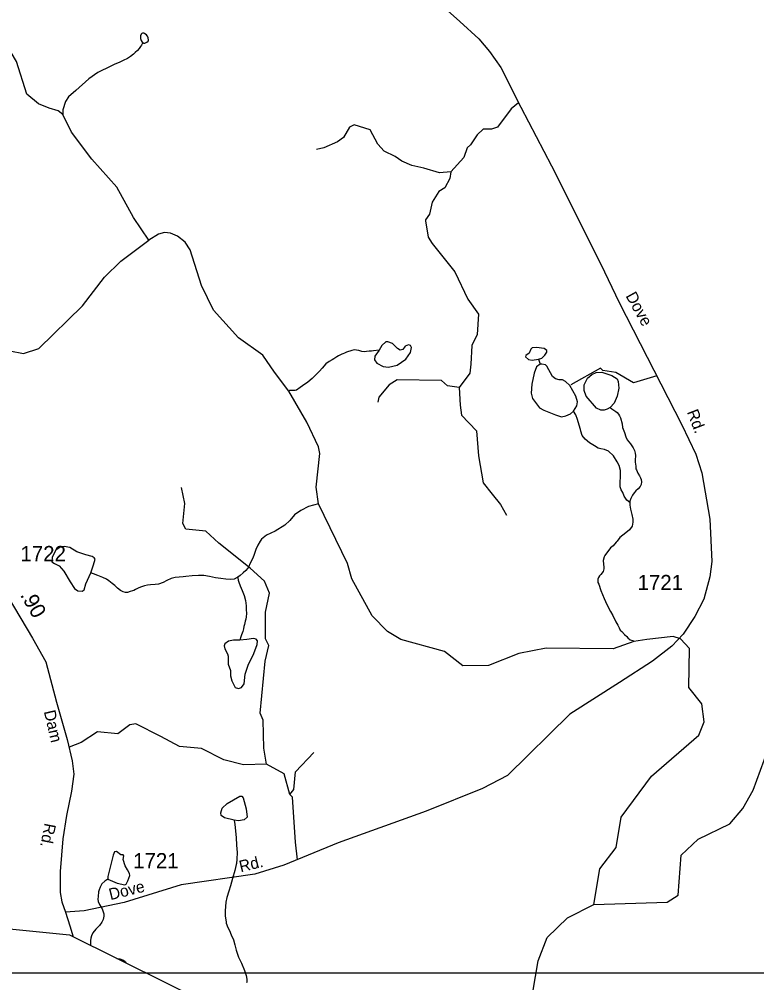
# Model space of a CAD drawing. Extents: x 2056842 to 2160602, y 826753 to 1016856.
# Drawn here: x 2093202 to 2099244, y 845771 to 853660 of the extents above; entities that cross this region are included whole.
import ezdxf

# ---------------------------------------------------------------- set-up
doc = ezdxf.new("R2010")
doc.units = 0
for name, color, linetype in [('Exist Boundary Political CountyLine', 7, 'Continuous'), ('Exist Hydrographic Creek Single Shore', 7, 'Continuous'), ('Exist Hydrographic Misc Water Feature', 7, 'Continuous'), ('Exist Road Non-System Type 51', 7, 'Continuous'), ('Exist Road Secondary Mileage Hundredths English Label', 7, 'Continuous'), ('Exist Road Secondary Type 51 Attributed', 7, 'Continuous'), ('Exist Road Secondary Type 51 Label', 7, 'Continuous'), ('Exist Road Secondary Type 51 Number Label', 7, 'Continuous'), ('Map Preparation Inset Cut Line', 7, 'Continuous')]:
    doc.layers.add(name, color=color, linetype=linetype)

msp = doc.modelspace()

# ---------------------------------------------------------------- linework, layer by layer
at = {"layer": 'Exist Boundary Political CountyLine'}
msp.add_lwpolyline([(2087202.4, 846841.6), (2088278.5, 846703.3), (2089060.9, 846620.9), (2089592.9, 846564), (2090401.1, 846475.5), (2091507.2, 846371.9), (2092417.4, 846283.6), (2093037.6, 846221), (2093614.4, 846162.7), (2094823.1, 845562.6), (2096040.2, 844956.3), (2096290.8, 844827.9), (2097736.3, 844110.3), (2098905.5, 843530.6), (2099954.7, 843014.5), (2100389.5, 842806.4), (2101933, 842032.5), (2102162, 841868.8), (2110170.3, 837920.8)], dxfattribs=at)
at = {"layer": 'Exist Hydrographic Creek Single Shore'}
for points in [[(2094262.8, 851850.9), (2094137.2, 852037.8), (2094000.5, 852284.8), (2093797.5, 852514.6), (2093629.1, 852735.1), (2093557.8, 852881.1), (2093520.2, 852910.4), (2093445.5, 852933.2), (2093359.2, 852968.7), (2093264.2, 853045.4), (2093180.1, 853313), (2093099.6, 853448.9), (2092973, 853489.4), (2092829.3, 853562.9), (2092762.2, 853679.2), (2092728.2, 853870.2), (2092751.4, 854356.6), (2092797, 854536.5)], [(2095654.2, 849692.2), (2095635.2, 849828.1), (2095664.1, 850105.4), (2095654.2, 850159.4), (2095558, 850360.9), (2095409.7, 850615.9), (2095292, 850771.6), (2095198.3, 850908.4), (2094999.1, 851052.4), (2094792.7, 851277.9), (2094695.2, 851479.3), (2094600.9, 851772.4), (2094560.4, 851834.4), (2094499.6, 851883.8), (2094441.4, 851907.9), (2094392, 851913), (2094341.3, 851900.3), (2094262.8, 851850.9)], [(2092899.2, 850987.5), (2093237.1, 850923.1), (2093362.2, 850963.2), (2093719.2, 851313.5), (2093899.2, 851549.4), (2094034.7, 851679.9), (2094262.8, 851850.9)], [(2097909.2, 846410.6), (2097958.2, 846704.9), (2098091.1, 846879.4), (2098132.1, 847127.8), (2098381, 847463.9), (2098771, 847797.1), (2098813, 847907.8), (2098795, 848055.8), (2098687.1, 848189.4), (2098694.1, 848507.4), (2098619.1, 848587.7), (2098560, 848605.4), (2098344.1, 848580.3), (2098236.5, 848566.1), (2098069.1, 848503.9), (2097519.2, 848511.9), (2097294, 848467.3), (2097045.1, 848367.5), (2096836.2, 848365.2), (2096686.1, 848483.1), (2096327, 848582.4), (2096219.2, 848647), (2096094.1, 848774.2), (2095926.1, 849079.5), (2095892.1, 849204.9), (2095654.2, 849692.2)], [(2098205.1, 849702.1), (2098203, 849680.1), (2098209.2, 849650), (2098221.5, 849604.3), (2098229.7, 849566.1), (2098229.5, 849542.2), (2098223.3, 849508.2), (2098201.6, 849479.9), (2098171.9, 849454), (2098123.7, 849417.8), (2098100.1, 849387.8), (2098091.9, 849377.6), (2098068.1, 849349.6), (2098046.2, 849331.8), (2098024, 849301.5), (2098012.3, 849289.5), (2097998.4, 849269.6), (2097994.1, 849259.3), (2097986.1, 849229.3), (2097988.3, 849197.3), (2097992.6, 849173.6), (2097992.6, 849159.3), (2097984.9, 849137.4), (2097966.8, 849113.3), (2097954.9, 849103.4), (2097947.1, 849089.2), (2097941, 849075.5), (2097943, 849047.2), (2097949.2, 849033.3), (2097967.2, 848983.4), (2097995.3, 848917.5), (2098015.6, 848867.4), (2098046.2, 848811.7), (2098063.8, 848777.7), (2098090, 848725.8), (2098105.8, 848697.9), (2098116.1, 848678.1), (2098125.9, 848657.9), (2098138.4, 848645.9), (2098160.4, 848621.9), (2098180.7, 848606.3), (2098188.3, 848596.2), (2098208.2, 848580.2), (2098228.5, 848572.2), (2098236.5, 848566.1)], [(2097909.2, 846410.6), (2098509.2, 846431), (2098600, 846488.2), (2098624, 846815.8), (2098765.1, 846947.4), (2099023, 847073.4), (2099131.1, 847199.2), (2099214.1, 847348.3), (2099396, 847840.1)], [(2097373.2, 844551.5), (2097346.1, 845326.3), (2097452.1, 845950.8), (2097526.1, 846142.8), (2097693.1, 846303.5), (2097909.2, 846410.6)]]:
    msp.add_lwpolyline(points, dxfattribs=at)
at = {"layer": 'Exist Hydrographic Misc Water Feature'}
msp.add_line((2097455.1, 850876.2), (2097470.9, 850836.1), dxfattribs=at)
for points in [[(2094214.2, 853469), (2094220.3, 853465.2), (2094231.8, 853463), (2094248, 853471.1), (2094257.8, 853481.4), (2094260.1, 853489.2), (2094257.8, 853507.4), (2094251.7, 853521.2), (2094249.8, 853525.2), (2094243.9, 853533), (2094231.6, 853540.9), (2094223.8, 853545), (2094217.8, 853547.1), (2094211.9, 853547.2), (2094205.5, 853542.8), (2094201.6, 853537), (2094195.5, 853522.9), (2094193.9, 853513), (2094195.9, 853502.9), (2094201.8, 853487), (2094209.6, 853472.9), (2094214.2, 853469)], [(2094214.2, 853469), (2094212.3, 853463.1), (2094203.9, 853449), (2094196.1, 853437.2), (2094184, 853421.1), (2094169.9, 853405), (2094152.4, 853387), (2094138.1, 853374.9), (2094112.2, 853355), (2094088.2, 853338.7), (2094052.6, 853322.6), (2094026.3, 853308.7), (2093980.4, 853290.5), (2093952.7, 853274.4), (2093846.7, 853223.3), (2093770.7, 853171.4), (2093664.3, 853077.7), (2093606.1, 853025.7), (2093579.5, 852987.7), (2093560, 852919.3), (2093559.6, 852915.3), (2093557.6, 852905), (2093558, 852897.3), (2093558, 852889.2), (2093557.8, 852881.1)], [(2096151.2, 850950.3), (2096115.7, 850900.8), (2096111.9, 850870.4), (2096132.2, 850845.1), (2096182.8, 850817.2), (2096225.9, 850812.2), (2096299.3, 850828.6), (2096370.2, 850876.8), (2096408.2, 850932.5), (2096415.8, 850973.1), (2096408.2, 850989.5), (2096391.8, 850993.3), (2096363.9, 850983.2), (2096343.7, 850955.3), (2096323.4, 850950.3), (2096301.9, 850962.9), (2096260.1, 851006), (2096220.8, 851018.7), (2096204.4, 851017.4), (2096172.7, 850988.3), (2096151.2, 850950.3)], [(2096151.2, 850950.3), (2096103.5, 850945.3), (2096087.3, 850943.3), (2096067.4, 850941), (2096047.5, 850939.2), (2096027.2, 850937), (2096009.6, 850938.8), (2095983.3, 850946.9), (2095965.3, 850950.8), (2095947.5, 850952.7), (2095925.5, 850948.7), (2095883.7, 850934.8), (2095867.5, 850924.7), (2095853.7, 850920.7), (2095843.7, 850916.5), (2095817.9, 850904.2), (2095803.7, 850896.2), (2095779.7, 850880.3), (2095765.8, 850872.3), (2095739.7, 850856.4), (2095713.7, 850838), (2095684, 850802), (2095662, 850778.1), (2095628.2, 850745.9), (2095602.1, 850719.8), (2095586.2, 850705.6), (2095562.6, 850685.6), (2095540.2, 850671.5), (2095522.6, 850657.6), (2095502.3, 850645.6), (2095472.8, 850623.4), (2095462.7, 850619.2), (2095452.5, 850619.1), (2095436.7, 850621.1), (2095422.5, 850621.2), (2095414.7, 850619.2), (2095409.7, 850615.9)], [(2097455.1, 850876.2), (2097482.6, 850886.1), (2097507.9, 850910.2), (2097525.6, 850934.3), (2097524.3, 850948.2), (2097502.8, 850963.4), (2097439.5, 850972.3), (2097404.1, 850968.5), (2097392.7, 850959.6), (2097380, 850925.4), (2097350.9, 850907.7), (2097348.3, 850896.3), (2097373.7, 850873.5), (2097404.1, 850868.4), (2097455.1, 850876.2)], [(2097744.1, 850452.2), (2097770, 850494.7), (2097775, 850527.6), (2097761.1, 850573.2), (2097711.7, 850660.6), (2097677.5, 850693.6), (2097653.5, 850708.8), (2097624.4, 850708.8), (2097594, 850715.1), (2097569.9, 850735.4), (2097524.3, 850820.3), (2097512.9, 850830.4), (2097483.8, 850836.7), (2097470.9, 850836.1)], [(2097470.9, 850836.1), (2097439.5, 850812.7), (2097419.3, 850763.2), (2097400.3, 850673.3), (2097395.2, 850599.8), (2097407.9, 850554.2), (2097464.8, 850479.5), (2097500.3, 850457.9), (2097595.2, 850421.2), (2097643.4, 850404.7), (2097681.3, 850412.3), (2097718.1, 850430.1), (2097744.1, 850452.2)], [(2098043.8, 850480.7), (2098018.1, 850466.8), (2097994.1, 850457.9), (2097967.5, 850457.9), (2097930.8, 850475.7), (2097847.2, 850573.2), (2097830.8, 850621.4), (2097830.8, 850667), (2097857.3, 850720.2), (2097892.8, 850750.6), (2097929.5, 850768.3), (2097973.8, 850770.9), (2098056.1, 850743), (2098100.4, 850715.1), (2098109.3, 850694.8), (2098113.1, 850639.1), (2098100.4, 850574.5), (2098075.1, 850516.2), (2098043.8, 850480.7)], [(2098205.1, 849702.1), (2098178.6, 849721.9), (2098156.7, 849756.1), (2098146.4, 849784), (2098132.5, 849807.7), (2098126.3, 849831.7), (2098124.9, 849845.7), (2098124.5, 849873.8), (2098126.5, 849911.6), (2098128.4, 849965.7), (2098117.9, 850005.8), (2098100.1, 850035.7), (2098070.2, 850085.7), (2098029.6, 850123.5), (2097997.6, 850137.3), (2097967.4, 850143.1), (2097943.8, 850149.1), (2097913.7, 850167.1), (2097873.7, 850192.9), (2097839.3, 850220.9), (2097813.6, 850252.8), (2097803.2, 850286.9), (2097801.1, 850300.5), (2097789.4, 850336.8), (2097776.9, 850382.5), (2097763, 850420.3), (2097744.1, 850452.2)], [(2098043.8, 850480.7), (2098056.6, 850469.6), (2098088.8, 850447.7), (2098100.5, 850439.8), (2098112.6, 850427.8), (2098120.8, 850413.6), (2098129, 850395.7), (2098140.9, 850347.7), (2098145.2, 850317.8), (2098161.2, 850275.6), (2098171.5, 850242), (2098183.1, 850215.9), (2098209.2, 850183.9), (2098231.5, 850152.1), (2098243.6, 850128), (2098247.7, 850106.3), (2098249.8, 850088.1), (2098247.7, 850050.3), (2098248.1, 850034), (2098252.2, 850000.1), (2098252.2, 849989.9), (2098253.9, 849979.9), (2098258.2, 849972), (2098270.1, 849944.2), (2098282.6, 849922.1), (2098292.2, 849904.3), (2098296.3, 849890.3), (2098300.6, 849872.2), (2098296.5, 849850.1), (2098288.7, 849834.3), (2098272.5, 849816.5), (2098252.4, 849798), (2098238.9, 849782.2), (2098226.8, 849764.1), (2098212.9, 849736.2), (2098204.9, 849713.9), (2098205.1, 849702.1)], [(2095654.2, 849692.2), (2095571.9, 849670.7), (2095509.9, 849637.7), (2095456.7, 849601), (2095418.7, 849556.6), (2095376.9, 849518.6), (2095297.2, 849469.2), (2095226.3, 849436.3), (2095185.7, 849402.1), (2095176.7, 849386.5), (2095156.6, 849352.6), (2095140.6, 849318.5), (2095126.6, 849278.4), (2095114.9, 849248.5), (2095093, 849206.4), (2095079.3, 849174.4), (2095072.9, 849162.4), (2095057.1, 849146.1), (2095035.2, 849126.3), (2095011.4, 849106), (2094993.3, 849092.1)], [(2093787, 849127.8), (2093810.5, 849193), (2093823.1, 849238.7), (2093815.5, 849251.3), (2093800.3, 849260.2), (2093745.9, 849275.4), (2093672.4, 849298.2), (2093615.5, 849333.7), (2093569.9, 849342.5), (2093537, 849337.5), (2093502.8, 849313.4), (2093471.1, 849255.1), (2093469.9, 849217.1), (2093490.1, 849203.2), (2093528.1, 849185.4), (2093567.3, 849142.4), (2093618, 849054.9), (2093653.4, 848997.9), (2093682.6, 848978.9), (2093716.8, 848976.4), (2093734.5, 848989.1), (2093748.4, 849038.5), (2093787, 849127.8)], [(2094993.3, 849092.1), (2094987.6, 849088.1), (2094961.4, 849075.9), (2094933.5, 849072), (2094893.7, 849075.6), (2094853.5, 849081.6), (2094809.4, 849087.5), (2094759.6, 849097.5), (2094713.2, 849105.3), (2094669.6, 849105), (2094617.3, 849102.8), (2094567.5, 849097), (2094545.3, 849094.6), (2094479.3, 849088.4), (2094445.2, 849080.6), (2094411.6, 849064.2), (2094379.6, 849048.3), (2094343.5, 849036), (2094315.7, 849032.1), (2094275.9, 849030), (2094253.7, 849027.7), (2094227.7, 849021.9), (2094203.9, 849013.7), (2094181.8, 849003.7), (2094155.5, 848991.4), (2094141.8, 848983.3), (2094129.7, 848979.5), (2094111.6, 848973.3), (2094089.9, 848967.3), (2094072.1, 848967.1), (2094054, 848971.1), (2094031.7, 848983), (2094005.8, 849001.1), (2093983.9, 849024.8), (2093961.9, 849040.7), (2093935.9, 849062.9), (2093915.8, 849074.8), (2093887.3, 849088.5), (2093845.5, 849106.6), (2093809.4, 849120.6), (2093787, 849127.8)], [(2094993.3, 849092.1), (2094993.1, 849086), (2094995.6, 849068.2), (2094999.5, 849050.2), (2095011.6, 849020.4), (2095027.6, 848982.2), (2095045.6, 848942.1), (2095056.1, 848900.4), (2095062.2, 848858.5), (2095062, 848826.5), (2095064.5, 848794.4), (2095060.6, 848766.2), (2095058.4, 848748.3), (2095052.8, 848732.5), (2095046.5, 848704.3), (2095042.6, 848688.2), (2095038.7, 848670.1), (2095032.9, 848648.3), (2095023.1, 848620.1), (2095016.9, 848604), (2095008.2, 848574.8)], [(2095008.2, 848574.8), (2094957.6, 848576.1), (2094917.1, 848567.2), (2094886.7, 848545.7), (2094881.6, 848530.4), (2094886.7, 848505.1), (2094908.2, 848463.3), (2094913.3, 848444.3), (2094914.5, 848379.7), (2094933.5, 848327.7), (2094933.5, 848283.4), (2094942.4, 848242.9), (2094970.3, 848188.4), (2094999.4, 848179.5), (2095022.2, 848188.4), (2095043.7, 848218.8), (2095053.8, 848298.6), (2095076.6, 848370.8), (2095123.5, 848467.1), (2095151.3, 848541.9), (2095152.6, 848569.7), (2095143.7, 848583.7), (2095120.9, 848590), (2095066.5, 848581.1), (2095008.2, 848574.8)], [(2094963.6, 847102.3), (2094883.6, 847121.8), (2094855.8, 847139.5), (2094852, 847162.3), (2094864.7, 847200.3), (2094906.4, 847239.6), (2095007.7, 847299.1), (2095024.2, 847299.1), (2095036.9, 847283.9), (2095062.2, 847194), (2095068.5, 847126.8), (2095043.2, 847105.3), (2094997.6, 847097.7), (2094963.6, 847102.3)], [(2094963.6, 847102.3), (2094969.4, 847068.2), (2094971.8, 847042.3), (2094973.7, 847012.4), (2094977.8, 846960.2), (2094981.9, 846898.3), (2094986.4, 846838.4), (2094984.5, 846784.3), (2094980.8, 846746.3), (2094978.6, 846740.2), (2094968.9, 846690.5), (2094949.1, 846624.2), (2094933.5, 846564), (2094919.3, 846522.4), (2094901.3, 846468.3), (2094893.7, 846430.1), (2094888, 846360.3), (2094888.2, 846320.1), (2094896.2, 846266.2), (2094898.2, 846258.2), (2094910.5, 846224.3), (2094924.5, 846198.2), (2094938.8, 846162.3), (2094956.9, 846122.3), (2094968.7, 846082.3), (2094979, 846038.6), (2094996.8, 845980.7), (2095022.9, 845932.5), (2095047.3, 845872.8), (2095061.6, 845830.9), (2095067.6, 845800.8), (2095065.7, 845778.7), (2095063.5, 845770.9)], [(2093927.9, 846619.3), (2094003.7, 846587.1), (2094065.7, 846573.2), (2094078.4, 846579.5), (2094091, 846604.9), (2094107.5, 846648), (2094106.2, 846665.7), (2094089.8, 846696.1), (2094069.5, 846729), (2094054.3, 846779.7), (2094058.1, 846811.4), (2094053, 846817.7), (2094035.3, 846819), (2093997.3, 846846.9), (2093983.4, 846841.8), (2093970.7, 846815.2), (2093945.4, 846717.6), (2093926.4, 846641.6), (2093927.9, 846619.3)], [(2093927.9, 846619.3), (2093927.5, 846619.1), (2093903.5, 846602.8), (2093879.5, 846581), (2093869.5, 846565), (2093863.7, 846552.9), (2093855.7, 846533), (2093851.8, 846514.9), (2093847.7, 846477), (2093846.1, 846454.9), (2093847.7, 846436.9), (2093860, 846413.1), (2093879.9, 846375.1), (2093888.1, 846353.2), (2093894.1, 846334.9), (2093894.1, 846317), (2093888.1, 846289.1), (2093878.1, 846267.1), (2093860.6, 846240.9), (2093828.4, 846208.9), (2093804.9, 846178.8), (2093792.8, 846154.7), (2093788.9, 846135), (2093786.8, 846116.6), (2093786.5, 846077.3)], [(2094001, 845970.8), (2094027.1, 845965.7), (2094055.2, 845955.4), (2094073.3, 845941.7), (2094077.8, 845932.7)]]:
    msp.add_lwpolyline(points, dxfattribs=at)
at = {"layer": 'Exist Road Non-System Type 51'}
for points in [[(2097291.9, 852976.9), (2097232, 852925.9), (2097119.8, 852776.2), (2097070, 852759.6), (2097003.5, 852759.6), (2096953.6, 852713.9), (2096899.6, 852630.7), (2096870.6, 852605.8), (2096845.6, 852526.8), (2096737.6, 852410.4)], [(2096737.6, 852410.4), (2096645.2, 852403.1), (2096516.4, 852440.5), (2096418.8, 852461.3), (2096335.7, 852498.7), (2096281.7, 852536.1), (2096192.4, 852579.8), (2096138.4, 852638), (2096078.2, 852754.4), (2095945.3, 852796), (2095907.9, 852777.2), (2095858, 852692), (2095810.3, 852656.7), (2095696, 852606.8), (2095635.8, 852594.3)], [(2096737.6, 852410.4), (2096728.3, 852355.3), (2096688.8, 852280.5), (2096639, 852249.3), (2096585, 852162), (2096562.1, 852064.3), (2096528.9, 852016.5), (2096531, 852008.2), (2096551.7, 851875.2), (2096585, 851823.2), (2096770.9, 851591.5), (2096876.8, 851367), (2096964, 851246.5), (2096953.6, 851078.1), (2096909, 850987.7), (2096900.7, 850836), (2096894.5, 850761.2), (2096805.1, 850644.8)], [(2098425, 850740.8), (2098235.2, 850683.2), (2098089.8, 850766.3), (2097981.8, 850783), (2097965.1, 850803.8), (2097720.1, 850666.6)], [(2096805.1, 850644.8), (2096711.7, 850659.3), (2096661.8, 850703), (2096298.4, 850707.1), (2096231.9, 850665.5), (2096148.8, 850565.8), (2096138.4, 850524.2)], [(2096805.1, 850644.8), (2096813.4, 850499.3), (2096825.9, 850418.2), (2096948.5, 850291.4), (2096964, 850084.6), (2097003.5, 849864.3), (2097076.2, 849770.8), (2097144.7, 849687.6), (2097192.5, 849598.3)], [(2095227.7, 847561.4), (2095204.8, 847692.3), (2095200.7, 847921), (2095175.7, 847979.2), (2095217.3, 848403.2), (2095246.3, 848532), (2095219.3, 848588.1), (2095219.3, 848804.3), (2095252.6, 848962.3), (2095211, 849057.9), (2095094.7, 849165.9), (2094837.2, 849369.6), (2094729.2, 849469.4), (2094567.2, 849486), (2094542.2, 849531.8), (2094558.9, 849693.9), (2094529.8, 849826.9)], [(2095227.7, 847561.4), (2095038.6, 847555.2), (2094876.6, 847596.7), (2094693.9, 847688.2), (2094515.2, 847704.8), (2094361.5, 847787.9), (2094158, 847891.9), (2094108.1, 847883.5), (2094008.4, 847808.7), (2093842.3, 847825.3), (2093709.4, 847738.1), (2093609.7, 847698.8)], [(2095418.7, 847312), (2095452, 847353.5), (2095464.4, 847499), (2095614, 847657)], [(2095418.7, 847312), (2095373, 847482.4), (2095227.7, 847561.4)], [(2095480.5, 846778.6), (2095464.4, 846921.2), (2095439.5, 847291.2), (2095418.7, 847312)]]:
    msp.add_lwpolyline(points, dxfattribs=at)
at = {"layer": 'Exist Road Secondary Type 51 Attributed'}
for points in [[(2096382.7, 854027.2), (2096811.6, 853641.6), (2096967.4, 853498.2), (2097054.6, 853396.4), (2097148.1, 853265.5), (2097311.1, 852940.2), (2097562.4, 852460.1), (2097966.4, 851654.7), (2098118, 851340.9), (2098629.9, 850340.2), (2098744.2, 850099.1), (2098795.1, 849946.4), (2098859.4, 849566), (2098876.1, 849221), (2098859.4, 849094.2), (2098810.6, 848912.4), (2098737.9, 848769), (2098642.6, 848625.2), (2098548.9, 848527.9), (2098389, 848403.2), (2098119, 848228.6), (2097713, 847969.9), (2097201, 847467.9), (2096997.5, 847361.9), (2096536.4, 847174.9), (2095814.7, 846916.1), (2095370.2, 846733.2), (2095131.4, 846660.5), (2094528.1, 846574.2), (2094060.8, 846428.8), (2093733.6, 846361.2), (2093580, 846348.7)], [(2091830.2, 850007.7), (2091967.2, 849864.3), (2092087.7, 849806.1), (2092191.5, 849772.8), (2092401.3, 849720.9), (2092566.4, 849647.1), (2092657.8, 849584.7), (2092753.3, 849487), (2092878, 849306.2), (2093161.5, 848841.7), (2093311, 848592.3), (2093419, 848399), (2093507.3, 848067.5), (2093594.5, 847762), (2093636, 847589.5), (2093648.5, 847479.4), (2093630.8, 847339.1), (2093589.3, 847141.6), (2093558.1, 846948.3), (2093536.3, 846683.4), (2093536.3, 846508.8), (2093550.9, 846434), (2093580, 846348.7)], [(2093580, 846348.7), (2093616.3, 846237.6), (2093643.1, 846148.5)]]:
    msp.add_lwpolyline(points, dxfattribs=at)
at = {"layer": 'Map Preparation Inset Cut Line'}
msp.add_lwpolyline([(2059276.8, 845851.8), (2104036.2, 845851.8), (2104036.2, 868310.8), (2085975.1, 868308.6), (2085982, 877260.1), (2059276.8, 877260.1), (2059276.8, 845851.8)], dxfattribs=at)

# ---------------------------------------------------------------- texts
at = {"layer": 'Exist Road Secondary Mileage Hundredths English Label'}
msp.add_text('.90', height=125, rotation=299.57958, dxfattribs=at).set_placement((2093206.5, 848946.7))
at = {"layer": 'Exist Road Secondary Type 51 Label'}
for s, rotation, p in [('Dove', 299.05576, (2098167.2, 851395.4)), ('Rd.', 291.0701, (2098670.4, 850444.5)), ('Dam', 283.19454, (2093402.7, 847992)), ('Rd.', 259.01328, (2093410.5, 847082.8)), ('Rd.', 13.57984, (2095015.9, 846675.2)), ('Dove', 13.95521, (2093949, 846446.9))]:
    msp.add_text(s, height=95, rotation=rotation, dxfattribs=at).set_placement(p)
at = {"layer": 'Exist Road Secondary Type 51 Number Label'}
for s, p in [('1722', (2093211.8, 849222.3)), ('1721', (2098268, 848985.6)), ('1721', (2094135.2, 846707.8))]:
    msp.add_text(s, height=125, dxfattribs=at).set_placement(p)

doc.saveas('drawing.dxf')
